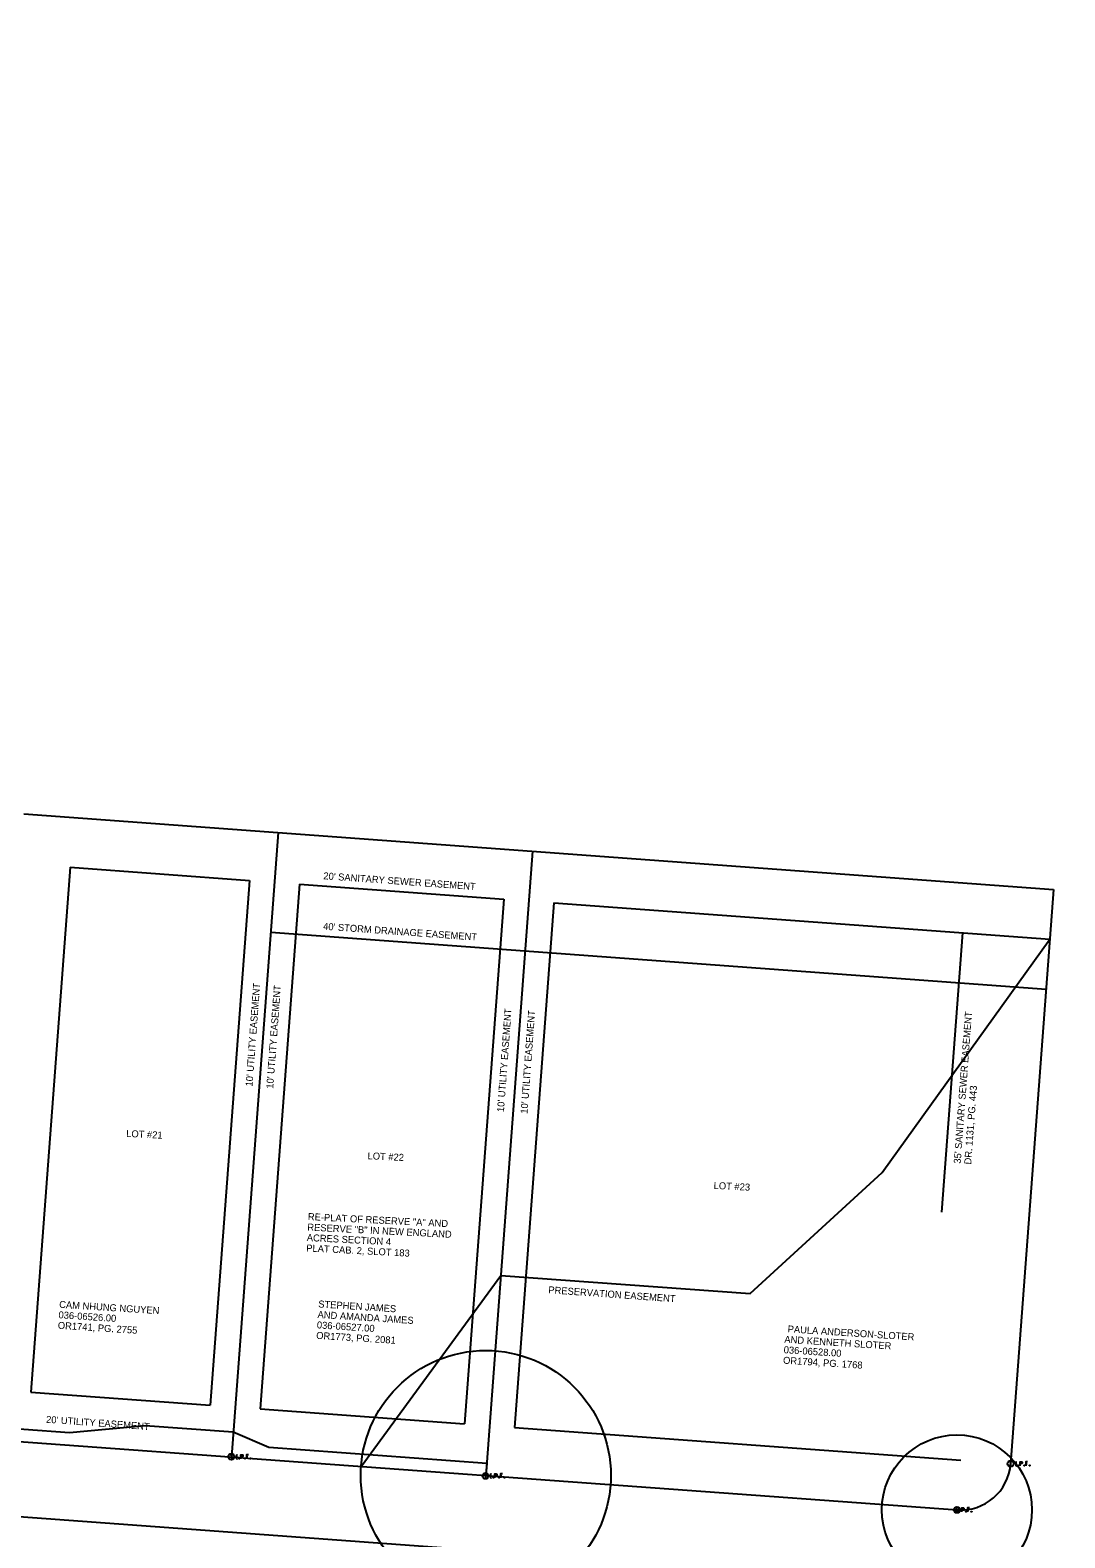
# Model space of a CAD drawing. Extents: x 1898254 to 1901377, y 701554 to 704886.
# Drawn here: x 1900233 to 1900647, y 703191 to 703794 of the extents above; entities that cross this region are included whole.
import ezdxf

# ---------------------------------------------------------------- set-up
doc = ezdxf.new("R2010")
doc.units = 0
for name, color, linetype in [('DV_X_Property_Line', 7, 'Continuous'), ('DV_X_Text', 7, 'Continuous'), ('RW_X_CL', 7, 'Continuous'), ('RW_X_Esmt_SC', 7, 'Continuous'), ('RW_X_Esmt_SW', 7, 'Continuous'), ('RW_X_Esmt_U', 7, 'Continuous'), ('RW_X_Fee_RW', 7, 'Continuous'), ('SC_Scratch1', 7, 'Continuous'), ('SC_Scratch2', 7, 'Continuous'), ('SC_Scratch3', 7, 'Continuous'), ('SC_Scratch6', 7, 'Continuous'), ('SV_P_Mon_Cells_Set', 7, 'Continuous'), ('SV_X_Mon_Cells_Found', 7, 'Continuous')]:
    doc.layers.add(name, color=color, linetype=linetype)

msp = doc.modelspace()

# ---------------------------------------------------------------- linework, layer by layer
at = {"layer": 'DV_X_Property_Line'}
for p, q in [((1900230.87, 703480.71), (1900642.66, 703450.49)), ((1900332.6, 703473.25), (1900313.88, 703223.51)), ((1900434.32, 703465.78), (1900415.61, 703216.07))]:
    msp.add_line(p, q, dxfattribs=at)
at = {"layer": 'RW_X_CL'}
msp.add_line((1899815.76, 703229.84), (1901162.17, 703131.42), dxfattribs=at)
at = {"layer": 'RW_X_Esmt_SC'}
for p, q in [((1900574.06, 703337.18), (1900641.2, 703430.54)), ((1900521.34, 703288.81), (1900574.06, 703337.18)), ((1900365.74, 703219.72), (1900421.6, 703296.1)), ((1900421.6, 703296.1), (1900521.34, 703288.81))]:
    msp.add_line(p, q, dxfattribs=at)
at = {"layer": 'RW_X_Esmt_SW'}
for p, q in [((1900249.32, 703459.31), (1900321.13, 703454.03)), ((1900341.07, 703452.57), (1900422.85, 703446.57)), ((1900442.8, 703445.1), (1900641.2, 703430.54)), ((1900606.27, 703433.11), (1900597.92, 703321.4))]:
    msp.add_line(p, q, dxfattribs=at)
at = {"layer": 'RW_X_Esmt_U'}
for p, q in [((1900249.32, 703459.31), (1900233.59, 703249.43)), ((1900321.13, 703454.03), (1900305.4, 703244.18)), ((1900341.07, 703452.57), (1900325.35, 703242.72)), ((1900422.85, 703446.57), (1900407.13, 703236.74)), ((1900442.8, 703445.1), (1900427.08, 703235.29)), ((1900233.59, 703249.43), (1900305.4, 703244.18)), ((1900325.35, 703242.72), (1900407.13, 703236.74)), ((1900427.08, 703235.29), (1900605.56, 703222.24))]:
    msp.add_line(p, q, dxfattribs=at)
at = {"layer": 'RW_X_Fee_RW'}
for p, q in [((1900642.66, 703450.49), (1900625.5, 703220.75)), ((1899817.95, 703259.76), (1900604.1, 703202.29))]:
    msp.add_line(p, q, dxfattribs=at)
msp.add_arc((1900605.56, 703222.24), 20, 265.81918, 355.7289, dxfattribs=at)
at = {"layer": 'SC_Scratch1'}
msp.add_circle((1900604.03, 703202.3), 30, dxfattribs=at)
at = {"layer": 'SC_Scratch2'}
msp.add_circle((1899815.76, 703229.84), 1561.35, dxfattribs=at)
at = {"layer": 'SC_Scratch3'}
msp.add_circle((1900415.61, 703216.07), 50, dxfattribs=at)
at = {"layer": 'SC_Scratch6'}
msp.add_line((1900329.61, 703433.36), (1900639.68, 703410.6), dxfattribs=at)
at = {"layer": 'SV_P_Mon_Cells_Set'}
msp.add_lwpolyline([(1900212.15, 703230.94), (1900212.52, 703235.93), (1900249.06, 703233.26), (1900279.35, 703236.06), (1900314.63, 703233.48), (1900328.85, 703227.43), (1900415.98, 703221.06), (1900415.61, 703216.07)], dxfattribs=at)
at = {"layer": 'SV_X_Mon_Cells_Found'}
for p, q in [((1900313.87, 703223.67), (1900313.87, 703222.79)), ((1900625.51, 703220.87), (1900625.51, 703219.99)), ((1900415.48, 703216.01), (1900415.48, 703215.13))]:
    msp.add_line(p, q, dxfattribs=at)
for points in [[(1900315.9, 703224.36), (1900316.25, 703224.36)], [(1900315.9, 703222.76), (1900316.25, 703222.76)], [(1900316.07, 703222.76), (1900316.07, 703224.36)], [(1900317.03, 703222.97), (1900317.09, 703222.97), (1900317.12, 703222.95), (1900317.15, 703222.9), (1900317.15, 703222.83), (1900317.12, 703222.78), (1900317.09, 703222.76), (1900317.03, 703222.76), (1900317, 703222.78), (1900316.97, 703222.83), (1900316.97, 703222.9), (1900317, 703222.95), (1900317.03, 703222.97)], [(1900317.64, 703222.76), (1900317.64, 703224.36), (1900318.17, 703224.36), (1900318.22, 703224.34), (1900318.3, 703224.32), (1900318.33, 703224.29), (1900318.37, 703224.27), (1900318.41, 703224.21), (1900318.44, 703224.14), (1900318.46, 703224.04), (1900318.46, 703223.89), (1900318.45, 703223.84), (1900318.43, 703223.76), (1900318.39, 703223.68), (1900318.34, 703223.64), (1900318.31, 703223.61), (1900318.25, 703223.59), (1900318.17, 703223.58), (1900317.64, 703223.58)], [(1900319.28, 703222.97), (1900319.34, 703222.97), (1900319.37, 703222.95), (1900319.4, 703222.9), (1900319.4, 703222.83), (1900319.37, 703222.78), (1900319.34, 703222.76), (1900319.28, 703222.76), (1900319.25, 703222.78), (1900319.21, 703222.83), (1900319.21, 703222.9), (1900319.25, 703222.95), (1900319.28, 703222.97)], [(1900320.65, 703224.36), (1900319.89, 703224.36), (1900319.89, 703222.76)], [(1900319.89, 703223.58), (1900320.43, 703223.58)], [(1900321.43, 703222.97), (1900321.48, 703222.97), (1900321.52, 703222.95), (1900321.55, 703222.9), (1900321.55, 703222.83), (1900321.52, 703222.78), (1900321.48, 703222.76), (1900321.43, 703222.76), (1900321.4, 703222.78), (1900321.36, 703222.83), (1900321.36, 703222.9), (1900321.4, 703222.95), (1900321.43, 703222.97)], [(1900627.54, 703221.56), (1900627.89, 703221.56)], [(1900627.71, 703219.96), (1900627.71, 703221.56)], [(1900629.28, 703219.96), (1900629.28, 703221.56), (1900629.81, 703221.56), (1900629.86, 703221.54), (1900629.94, 703221.52), (1900629.97, 703221.49), (1900630, 703221.47), (1900630.05, 703221.4), (1900630.08, 703221.34), (1900630.1, 703221.24), (1900630.1, 703221.09), (1900630.09, 703221.04), (1900630.07, 703220.96), (1900630.03, 703220.88), (1900629.98, 703220.84), (1900629.95, 703220.81), (1900629.89, 703220.79), (1900629.81, 703220.78), (1900629.28, 703220.78)], [(1900632.29, 703221.56), (1900631.53, 703221.56), (1900631.53, 703219.96)], [(1900631.53, 703220.78), (1900632.07, 703220.78)], [(1900417.51, 703216.69), (1900417.86, 703216.69)], [(1900417.51, 703215.09), (1900417.86, 703215.09)], [(1900417.68, 703215.09), (1900417.68, 703216.69)], [(1900418.64, 703215.31), (1900418.7, 703215.31), (1900418.73, 703215.28), (1900418.76, 703215.23), (1900418.76, 703215.17), (1900418.73, 703215.12), (1900418.7, 703215.09), (1900418.64, 703215.09), (1900418.61, 703215.12), (1900418.58, 703215.17), (1900418.58, 703215.23), (1900418.61, 703215.28), (1900418.64, 703215.31)], [(1900419.25, 703215.09), (1900419.25, 703216.69), (1900419.78, 703216.69), (1900419.83, 703216.68), (1900419.91, 703216.66), (1900419.94, 703216.63), (1900419.98, 703216.61), (1900420.02, 703216.54), (1900420.05, 703216.48), (1900420.08, 703216.38), (1900420.08, 703216.23), (1900420.06, 703216.18), (1900420.04, 703216.1), (1900420, 703216.01), (1900419.95, 703215.98), (1900419.92, 703215.95), (1900419.87, 703215.93), (1900419.78, 703215.91), (1900419.25, 703215.91)], [(1900420.89, 703215.31), (1900420.95, 703215.31), (1900420.98, 703215.28), (1900421.01, 703215.23), (1900421.01, 703215.17), (1900420.98, 703215.12), (1900420.95, 703215.09), (1900420.89, 703215.09), (1900420.86, 703215.12), (1900420.83, 703215.17), (1900420.83, 703215.23), (1900420.86, 703215.28), (1900420.89, 703215.31)], [(1900422.26, 703216.69), (1900421.5, 703216.69), (1900421.5, 703215.09)], [(1900421.5, 703215.91), (1900422.04, 703215.91)], [(1900423.04, 703215.31), (1900423.1, 703215.31), (1900423.13, 703215.28), (1900423.16, 703215.23), (1900423.16, 703215.17), (1900423.13, 703215.12), (1900423.1, 703215.09), (1900423.04, 703215.09), (1900423.01, 703215.12), (1900422.98, 703215.17), (1900422.98, 703215.23), (1900423.01, 703215.28), (1900423.04, 703215.31)], [(1900627.54, 703219.96), (1900627.89, 703219.96)], [(1900628.67, 703220.17), (1900628.73, 703220.17), (1900628.76, 703220.15), (1900628.79, 703220.09), (1900628.79, 703220.03), (1900628.76, 703219.98), (1900628.73, 703219.96), (1900628.67, 703219.96), (1900628.64, 703219.98), (1900628.61, 703220.03), (1900628.61, 703220.09), (1900628.64, 703220.15), (1900628.67, 703220.17)], [(1900630.92, 703220.17), (1900630.97, 703220.17), (1900631.01, 703220.15), (1900631.04, 703220.09), (1900631.04, 703220.03), (1900631.01, 703219.98), (1900630.97, 703219.96), (1900630.92, 703219.96), (1900630.89, 703219.98), (1900630.85, 703220.03), (1900630.85, 703220.09), (1900630.89, 703220.15), (1900630.92, 703220.17)], [(1900633.07, 703220.17), (1900633.12, 703220.17), (1900633.16, 703220.15), (1900633.19, 703220.09), (1900633.19, 703220.03), (1900633.16, 703219.98), (1900633.12, 703219.96), (1900633.07, 703219.96), (1900633.04, 703219.98), (1900633, 703220.03), (1900633, 703220.09), (1900633.04, 703220.15), (1900633.07, 703220.17)], [(1900606.02, 703201.5), (1900606.02, 703203.1), (1900606.55, 703203.1), (1900606.61, 703203.09), (1900606.68, 703203.06), (1900606.72, 703203.03), (1900606.75, 703203.01), (1900606.8, 703202.95), (1900606.83, 703202.88), (1900606.85, 703202.78), (1900606.85, 703202.63), (1900606.84, 703202.58), (1900606.82, 703202.51), (1900606.77, 703202.42), (1900606.73, 703202.38), (1900606.7, 703202.35), (1900606.64, 703202.33), (1900606.55, 703202.32), (1900606.02, 703202.32)], [(1900609.03, 703203.1), (1900608.27, 703203.1), (1900608.27, 703201.5)], [(1900608.27, 703202.32), (1900608.81, 703202.32)], [(1900607.67, 703201.71), (1900607.72, 703201.71), (1900607.75, 703201.69), (1900607.79, 703201.64), (1900607.79, 703201.57), (1900607.75, 703201.52), (1900607.72, 703201.5), (1900607.67, 703201.5), (1900607.63, 703201.52), (1900607.6, 703201.57), (1900607.6, 703201.64), (1900607.63, 703201.69), (1900607.67, 703201.71)], [(1900609.82, 703201.71), (1900609.87, 703201.71), (1900609.9, 703201.69), (1900609.94, 703201.64), (1900609.94, 703201.57), (1900609.9, 703201.52), (1900609.87, 703201.5), (1900609.82, 703201.5), (1900609.78, 703201.52), (1900609.75, 703201.57), (1900609.75, 703201.64), (1900609.78, 703201.69), (1900609.82, 703201.71)]]:
    msp.add_lwpolyline(points, dxfattribs=at)
for centre, radius in [((1900313.87, 703223.56), 1.2), ((1900313.87, 703224.21), 0.16), ((1900625.51, 703220.76), 1.2), ((1900625.51, 703221.41), 0.16), ((1900415.48, 703215.89), 1.2), ((1900415.48, 703216.55), 0.16), ((1900604.03, 703202.3), 1.2), ((1900604.03, 703202.3), 0.495)]:
    msp.add_circle(centre, radius, dxfattribs=at)

# ---------------------------------------------------------------- texts
at = {"layer": 'DV_X_Text'}
for s, rotation, p in [("20' SANITARY SEWER EASEMENT", 355.93252, (1900350.57, 703454.54)), ("40' STORM DRAINAGE EASEMENT", 355.93252, (1900350.48, 703434.37)), ("10' UTILITY EASEMENT", 85.7139, (1900322.29, 703371.55)), ("10' UTILITY EASEMENT", 85.7139, (1900330.57, 703370.68)), ("10' UTILITY EASEMENT", 85.7139, (1900422.85, 703361.34)), ("10' UTILITY EASEMENT", 85.7139, (1900432.27, 703360.67)), ("35' SANITARY SEWER EASEMENT", 85.7139, (1900605.51, 703340.69)), ('DR. 1131, PG. 443', 85.7139, (1900609.7, 703340.38)), ('LOT #21', 357.09486, (1900271.74, 703351.49)), ('LOT #22', 357.09486, (1900368.26, 703342.59)), ('LOT #23', 357.09486, (1900506.68, 703330.7)), ('RESERVE "B" IN NEW ENGLAND', 357.09486, (1900344.17, 703314.05)), ('RE-PLAT OF RESERVE "A" AND', 357.09486, (1900344.39, 703318.25)), ('ACRES SECTION 4', 357.09486, (1900343.96, 703309.86)), ('PLAT CAB. 2, SLOT 183', 357.09486, (1900343.75, 703305.67)), ('PRESERVATION EASEMENT', 355.93252, (1900440.54, 703288.97)), ('036-06526.00', 356.3351, (1900244.65, 703278.96)), ('CAM NHUNG NGUYEN ', 356.3351, (1900244.92, 703283.15)), ('AND AMANDA JAMES', 356.3351, (1900348.25, 703279.12)), ('STEPHEN JAMES ', 356.3351, (1900348.52, 703283.31)), ('OR1741, PG. 2755', 356.3351, (1900244.38, 703274.77)), ('036-06527.00', 356.3351, (1900347.98, 703274.93)), (' PAULA ANDERSON-SLOTER ', 356.3351, (1900535.22, 703273.38)), ('OR1773, PG. 2081', 356.3351, (1900347.71, 703270.74)), ('AND KENNETH SLOTER', 356.3351, (1900534.95, 703269.19)), ('OR1794, PG. 1768', 356.3351, (1900534.42, 703260.81)), ('036-06528.00', 356.3351, (1900534.68, 703265)), ("20' UTILITY EASEMENT", 355.93252, (1900239.67, 703237.17))]:
    msp.add_text(s, height=2.8, rotation=rotation, dxfattribs=at).set_placement(p)

doc.saveas('drawing.dxf')
